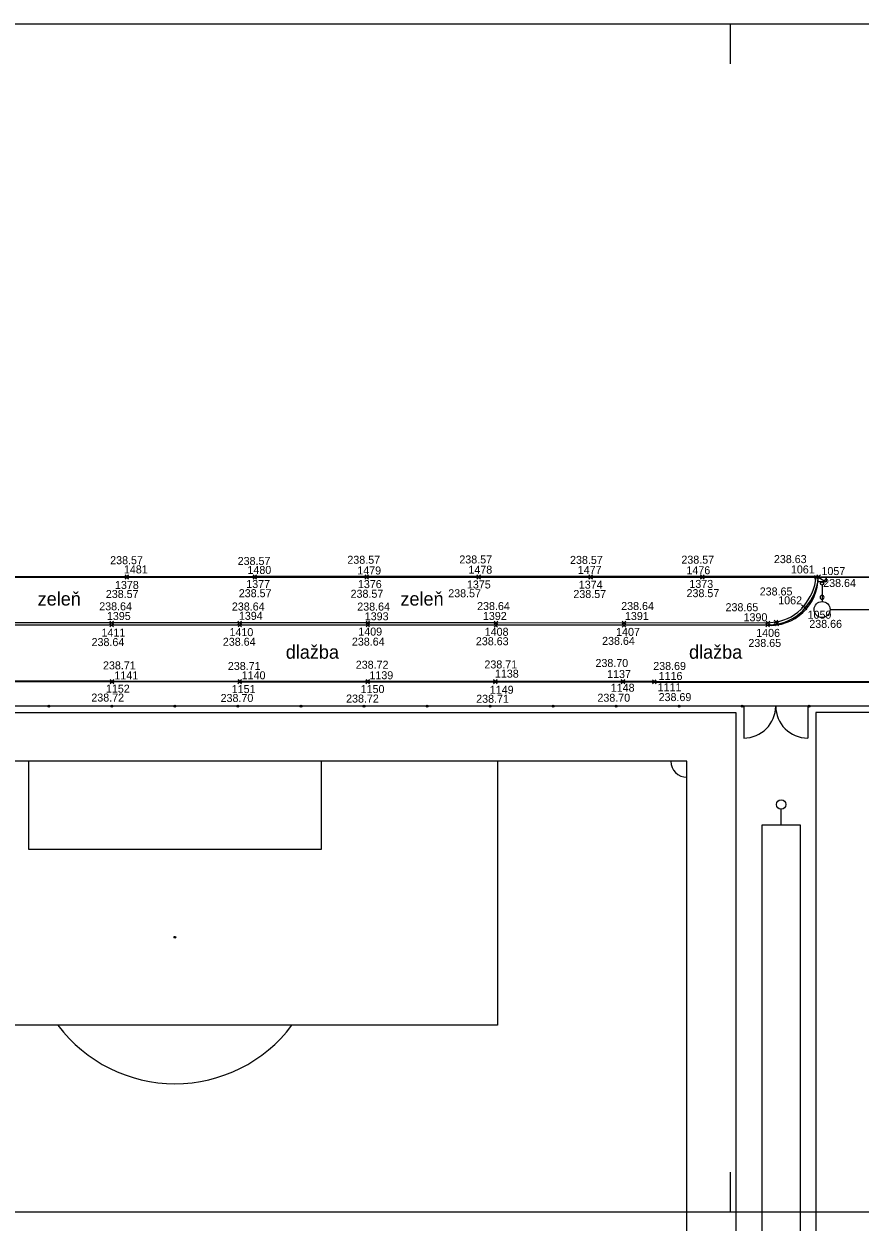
# Model space of a CAD drawing. Extents: x -264205 to -263659, y -1242401 to -1241986.
# Drawn here: x -264092.1 to -264039.8, y -1242219.8 to -1242144.9 of the extents above; entities that cross this region are included whole.
import ezdxf

# ---------------------------------------------------------------- set-up
doc = ezdxf.new("R2010")
doc.units = 0
for name, color, linetype in [('BOD_CISLO_2-1', 7, 'Continuous'), ('BOD_SYMBOL_2-1', 7, 'Continuous'), ('BOD_VYSKA_2-1', 7, 'Continuous'), ('POPIS_2-1', 7, 'Continuous'), ('PROJEKT_OBRUBNIKY_KOMUNIKACIE', 7, 'Continuous'), ('RAM_NA_TLAC_2-1_1-250', 7, 'Continuous'), ('SITUACIA_DSP_2D', 7, 'Continuous'), ('SO_20-4_OBRUBNIKY_HORNA_HRANA', 7, 'Continuous')]:
    doc.layers.add(name, color=color, linetype=linetype)

msp = doc.modelspace()

# ---------------------------------------------------------------- linework, layer by layer
at = {"layer": 'BOD_SYMBOL_2-1'}
for p, q in [((-264085.736, -1242179.559), (-264085.515, -1242179.339)), ((-264085.515, -1242179.559), (-264085.736, -1242179.339)), ((-264085.735, -1242179.603), (-264085.514, -1242179.383)), ((-264085.514, -1242179.603), (-264085.735, -1242179.383)), ((-264077.736, -1242179.556), (-264077.515, -1242179.335)), ((-264077.515, -1242179.556), (-264077.736, -1242179.335)), ((-264077.736, -1242179.6), (-264077.515, -1242179.38)), ((-264077.515, -1242179.6), (-264077.736, -1242179.38)), ((-264070.742, -1242179.596), (-264070.521, -1242179.374)), ((-264070.521, -1242179.596), (-264070.742, -1242179.374)), ((-264070.736, -1242179.549), (-264070.515, -1242179.328)), ((-264070.515, -1242179.549), (-264070.736, -1242179.328)), ((-264063.742, -1242179.548), (-264063.521, -1242179.326)), ((-264063.521, -1242179.548), (-264063.742, -1242179.326)), ((-264063.741, -1242179.596), (-264063.519, -1242179.376)), ((-264063.519, -1242179.596), (-264063.741, -1242179.376)), ((-264056.748, -1242179.552), (-264056.527, -1242179.33)), ((-264056.527, -1242179.552), (-264056.748, -1242179.33)), ((-264056.746, -1242179.597), (-264056.524, -1242179.377)), ((-264056.524, -1242179.597), (-264056.746, -1242179.377)), ((-264049.763, -1242179.556), (-264049.541, -1242179.335)), ((-264049.541, -1242179.556), (-264049.763, -1242179.335)), ((-264049.761, -1242179.6), (-264049.54, -1242179.38)), ((-264049.54, -1242179.6), (-264049.761, -1242179.38)), ((-264042.644, -1242179.597), (-264042.422, -1242179.377)), ((-264042.422, -1242179.597), (-264042.644, -1242179.377)), ((-264042.493, -1242179.552), (-264042.272, -1242179.332)), ((-264042.272, -1242179.552), (-264042.493, -1242179.332)), ((-264043.447, -1242181.421), (-264043.226, -1242181.2)), ((-264043.226, -1242181.421), (-264043.447, -1242181.2)), ((-264043.447, -1242181.421), (-264043.226, -1242181.2)), ((-264043.226, -1242181.421), (-264043.447, -1242181.2)), ((-264043.334, -1242181.511), (-264043.112, -1242181.289)), ((-264043.112, -1242181.511), (-264043.334, -1242181.289)), ((-264043.334, -1242181.511), (-264043.112, -1242181.289)), ((-264043.112, -1242181.511), (-264043.334, -1242181.289)), ((-264086.683, -1242182.59), (-264086.462, -1242182.369)), ((-264086.462, -1242182.59), (-264086.683, -1242182.369)), ((-264086.682, -1242182.441), (-264086.462, -1242182.221)), ((-264086.462, -1242182.441), (-264086.682, -1242182.221)), ((-264078.685, -1242182.441), (-264078.464, -1242182.221)), ((-264078.464, -1242182.441), (-264078.685, -1242182.221)), ((-264078.677, -1242182.585), (-264078.456, -1242182.363)), ((-264078.456, -1242182.585), (-264078.677, -1242182.363)), ((-264070.675, -1242182.59), (-264070.454, -1242182.37)), ((-264070.454, -1242182.59), (-264070.675, -1242182.37)), ((-264070.671, -1242182.447), (-264070.45, -1242182.225)), ((-264070.45, -1242182.447), (-264070.671, -1242182.225)), ((-264062.67, -1242182.593), (-264062.448, -1242182.373)), ((-264062.448, -1242182.593), (-264062.67, -1242182.373)), ((-264062.666, -1242182.451), (-264062.445, -1242182.23)), ((-264062.445, -1242182.451), (-264062.666, -1242182.23)), ((-264054.66, -1242182.6), (-264054.439, -1242182.379)), ((-264054.439, -1242182.6), (-264054.66, -1242182.379)), ((-264054.655, -1242182.454), (-264054.433, -1242182.232)), ((-264054.433, -1242182.454), (-264054.655, -1242182.232)), ((-264045.679, -1242182.588), (-264045.458, -1242182.367)), ((-264045.458, -1242182.588), (-264045.679, -1242182.367)), ((-264045.663, -1242182.445), (-264045.442, -1242182.225)), ((-264045.442, -1242182.445), (-264045.663, -1242182.225)), ((-264045.16, -1242182.377), (-264044.938, -1242182.157)), ((-264044.938, -1242182.377), (-264045.16, -1242182.157)), ((-264045.122, -1242182.516), (-264044.901, -1242182.296)), ((-264044.901, -1242182.516), (-264045.122, -1242182.296)), ((-264086.66, -1242186.09), (-264086.439, -1242185.869)), ((-264086.439, -1242186.09), (-264086.66, -1242185.869)), ((-264086.659, -1242186.136), (-264086.438, -1242185.914)), ((-264086.438, -1242186.136), (-264086.659, -1242185.914)), ((-264078.679, -1242186.144), (-264078.458, -1242185.924)), ((-264078.458, -1242186.144), (-264078.679, -1242185.924)), ((-264078.674, -1242186.1), (-264078.453, -1242185.879)), ((-264078.453, -1242186.1), (-264078.674, -1242185.879)), ((-264070.677, -1242186.144), (-264070.456, -1242185.923)), ((-264070.456, -1242186.144), (-264070.677, -1242185.923)), ((-264070.674, -1242186.096), (-264070.453, -1242185.876)), ((-264070.453, -1242186.096), (-264070.674, -1242185.876)), ((-264062.707, -1242186.099), (-264062.486, -1242185.877)), ((-264062.486, -1242186.099), (-264062.707, -1242185.877)), ((-264062.707, -1242186.141), (-264062.486, -1242185.921)), ((-264062.486, -1242186.141), (-264062.707, -1242185.921)), ((-264054.72, -1242186.096), (-264054.498, -1242185.874)), ((-264054.498, -1242186.096), (-264054.72, -1242185.874)), ((-264054.718, -1242186.14), (-264054.497, -1242185.92)), ((-264054.497, -1242186.14), (-264054.718, -1242185.92)), ((-264052.773, -1242186.103), (-264052.552, -1242185.882)), ((-264052.552, -1242186.103), (-264052.773, -1242185.882)), ((-264052.767, -1242186.149), (-264052.546, -1242185.927)), ((-264052.546, -1242186.149), (-264052.767, -1242185.927))]:
    msp.add_line(p, q, dxfattribs=at)
at = {"layer": 'PROJEKT_OBRUBNIKY_KOMUNIKACIE'}
for p, q in [((-263959.468, -1242179.482), (-264131.568, -1242179.482)), ((-264077.23, -1242179.482), (-264131.568, -1242179.482)), ((-264131.568, -1242179.482), (-263959.468, -1242179.482)), ((-263959.468, -1242179.482), (-264077.23, -1242179.482)), ((-264045.204, -1242182.482), (-264131.568, -1242182.482))]:
    msp.add_line(p, q, dxfattribs=at)
for points in [[(-264117.668, -1242187.932), (-264047.568, -1242187.932), (-264047.568, -1242294.032), (-264117.668, -1242294.032), (-264117.668, -1242187.932)], [(-264042.568, -1242294.032), (-263972.468, -1242294.032), (-263972.468, -1242187.932), (-264042.568, -1242187.932), (-264042.568, -1242294.032)]]:
    msp.add_lwpolyline(points, dxfattribs=at)
msp.add_arc((-264045.411, -1242179.495), 2.994, 266.03136, 0.25001, dxfattribs=at)
at = {"layer": 'RAM_NA_TLAC_2-1_1-250'}
for p, q in [((-264047.913, -1242144.907), (-264047.913, -1242147.407)), ((-264047.913, -1242216.657), (-264047.913, -1242219.157))]:
    msp.add_line(p, q, dxfattribs=at)
msp.add_lwpolyline([(-264147.913, -1242144.907), (-263857.913, -1242144.907), (-263857.913, -1242219.157), (-264147.913, -1242219.157)], close=True, dxfattribs=at)
at = {"layer": 'SITUACIA_DSP_2D'}
for p, q in [((-264077.23, -1242179.482), (-264131.568, -1242179.482)), ((-264131.568, -1242179.482), (-263959.468, -1242179.482)), ((-263959.468, -1242179.482), (-264131.568, -1242179.482)), ((-263959.468, -1242179.482), (-264077.23, -1242179.482)), ((-264042.417, -1242179.482), (-264041.917, -1242179.482)), ((-264042.417, -1242179.772), (-264042.417, -1242179.482)), ((-264042.417, -1242179.482), (-264041.917, -1242179.772)), ((-264042.417, -1242179.482), (-264041.917, -1242179.772)), ((-264041.917, -1242179.482), (-264042.417, -1242179.482)), ((-264041.917, -1242179.482), (-264041.917, -1242179.772)), ((-264041.917, -1242179.772), (-264041.917, -1242179.482)), ((-264041.917, -1242179.772), (-264042.417, -1242179.772)), ((-264042.167, -1242179.972), (-264042.167, -1242181)), ((-264041.667, -1242181.5), (-264014.161, -1242181.5)), ((-264045.204, -1242182.482), (-264131.568, -1242182.482)), ((-263972.068, -1242187.532), (-264118.068, -1242187.532)), ((-264090.436, -1242187.532), (-264090.556, -1242187.532)), ((-264090.496, -1242187.592), (-264090.496, -1242187.472)), ((-264086.497, -1242187.532), (-264086.617, -1242187.532)), ((-264086.557, -1242187.592), (-264086.557, -1242187.472)), ((-264082.558, -1242187.532), (-264082.678, -1242187.532)), ((-264082.618, -1242187.592), (-264082.618, -1242187.472)), ((-264078.619, -1242187.532), (-264078.739, -1242187.532)), ((-264078.679, -1242187.592), (-264078.679, -1242187.472)), ((-264074.68, -1242187.532), (-264074.8, -1242187.532)), ((-264074.74, -1242187.592), (-264074.74, -1242187.472)), ((-264070.741, -1242187.532), (-264070.861, -1242187.532)), ((-264070.801, -1242187.592), (-264070.801, -1242187.472)), ((-264066.802, -1242187.532), (-264066.922, -1242187.532)), ((-264066.862, -1242187.592), (-264066.862, -1242187.472)), ((-264062.863, -1242187.532), (-264062.983, -1242187.532)), ((-264062.923, -1242187.592), (-264062.923, -1242187.472)), ((-264058.924, -1242187.532), (-264059.044, -1242187.532)), ((-264058.984, -1242187.592), (-264058.984, -1242187.472)), ((-264054.986, -1242187.532), (-264055.106, -1242187.532)), ((-264055.046, -1242187.592), (-264055.046, -1242187.472)), ((-264051.047, -1242187.532), (-264051.167, -1242187.532)), ((-264051.107, -1242187.592), (-264051.107, -1242187.472)), ((-264047.108, -1242187.532), (-264047.228, -1242187.532)), ((-264047.168, -1242187.592), (-264047.168, -1242187.472)), ((-264047.068, -1242187.532), (-264047.068, -1242189.532)), ((-264044.568, -1242187.532), (-264045.568, -1242187.532)), ((-264043.068, -1242187.532), (-264043.068, -1242189.532)), ((-264042.908, -1242187.532), (-264043.028, -1242187.532)), ((-264042.968, -1242187.592), (-264042.968, -1242187.472)), ((-264117.668, -1242187.932), (-264047.568, -1242187.932)), ((-264047.568, -1242187.932), (-264047.568, -1242294.032)), ((-263972.468, -1242187.932), (-264042.568, -1242187.932)), ((-264042.568, -1242187.932), (-264042.568, -1242294.032)), ((-264050.618, -1242190.982), (-264114.618, -1242190.982)), ((-264091.778, -1242190.982), (-264091.778, -1242196.482)), ((-264073.458, -1242196.482), (-264073.458, -1242190.982)), ((-264062.458, -1242190.982), (-264062.458, -1242207.482)), ((-264050.618, -1242290.982), (-264050.618, -1242190.982)), ((-264044.727, -1242194.982), (-264044.727, -1242193.982)), ((-264043.527, -1242194.982), (-264045.927, -1242194.982)), ((-264045.927, -1242194.982), (-264045.927, -1242293.982)), ((-264043.527, -1242293.982), (-264043.527, -1242194.982)), ((-264091.778, -1242196.482), (-264073.458, -1242196.482)), ((-264062.458, -1242207.482), (-264102.778, -1242207.482))]:
    msp.add_line(p, q, dxfattribs=at)
for centre, radius in [((-264042.167, -1242179.872), 0.1), ((-264042.167, -1242181.5), 0.5), ((-264090.496, -1242187.532), 0.06), ((-264086.557, -1242187.532), 0.06), ((-264082.618, -1242187.532), 0.06), ((-264078.679, -1242187.532), 0.06), ((-264074.74, -1242187.532), 0.06), ((-264070.801, -1242187.532), 0.06), ((-264066.862, -1242187.532), 0.06), ((-264062.923, -1242187.532), 0.06), ((-264058.984, -1242187.532), 0.06), ((-264055.046, -1242187.532), 0.06), ((-264051.107, -1242187.532), 0.06), ((-264047.168, -1242187.532), 0.06), ((-264042.968, -1242187.532), 0.06), ((-264044.727, -1242193.682), 0.3), ((-264082.618, -1242201.982), 0.06)]:
    msp.add_circle(centre, radius, dxfattribs=at)
for centre, radius, start, end in [((-264045.412, -1242179.495), 2.994, 266.03136, 0.25001), ((-264042.167, -1242180.736), 0.125, 0, 180), ((-264042.167, -1242180.736), 0.125, 180, 0), ((-264047.068, -1242187.532), 2, 270, 360), ((-264043.068, -1242187.532), 2, 180, 270), ((-264050.618, -1242190.982), 1, 180, 270), ((-264082.618, -1242201.982), 0.0303, 90, 270), ((-264082.618, -1242201.982), 0.0303, 270, 90), ((-264082.618, -1242201.982), 9.15, 216.94821, 323.05179)]:
    msp.add_arc(centre, radius, start, end, dxfattribs=at)
at = {"layer": 'SO_20-4_OBRUBNIKY_HORNA_HRANA'}
for p, q in [((-264045.568, -1242182.477), (-264045.012, -1242182.406)), ((-264045.552, -1242182.335), (-264045.049, -1242182.267))]:
    msp.add_line(p, q, dxfattribs=at)
for points in [[(-264042.383, -1242179.442), (-264049.652, -1242179.445), (-264056.638, -1242179.441), (-264063.632, -1242179.437), (-264070.626, -1242179.438), (-264077.626, -1242179.445), (-264085.626, -1242179.449), (-264093.626, -1242179.439), (-264101.625, -1242179.445), (-264109.615, -1242179.435), (-264117.612, -1242179.431), (-264120.602, -1242179.426), (-264126.121, -1242179.433), (-264131.733, -1242179.426)], [(-264045.552, -1242182.335), (-264054.544, -1242182.343), (-264062.556, -1242182.34), (-264070.561, -1242182.336), (-264078.574, -1242182.331), (-264086.572, -1242182.331), (-264094.586, -1242182.329), (-264102.573, -1242182.329), (-264108.577, -1242182.332), (-264114.576, -1242182.338), (-264117.588, -1242182.342), (-264119.607, -1242182.346), (-264120.588, -1242182.345), (-264122.586, -1242182.345), (-264127.589, -1242182.338), (-264131.6, -1242182.327), (-264131.589, -1242179.471)], [(-264042.533, -1242179.487), (-264049.65, -1242179.49), (-264056.635, -1242179.487), (-264063.63, -1242179.486), (-264070.632, -1242179.485), (-264077.626, -1242179.49), (-264085.624, -1242179.493), (-264093.625, -1242179.486), (-264101.626, -1242179.485), (-264109.614, -1242179.478), (-264117.62, -1242179.479), (-264120.6, -1242179.475), (-264126.132, -1242179.477), (-264131.589, -1242179.471)], [(-264045.568, -1242182.477), (-264054.55, -1242182.489), (-264062.559, -1242182.483), (-264070.564, -1242182.48), (-264078.567, -1242182.474), (-264086.573, -1242182.479), (-264094.593, -1242182.473), (-264102.574, -1242182.476), (-264108.578, -1242182.479), (-264114.569, -1242182.481), (-264117.587, -1242182.486), (-264119.603, -1242182.49), (-264120.584, -1242182.487), (-264122.587, -1242182.488), (-264127.582, -1242182.481), (-264131.601, -1242182.479), (-264131.604, -1242183.314), (-264131.618, -1242187.312), (-264131.63, -1242191.337)], [(-264052.662, -1242185.992), (-264054.609, -1242185.985), (-264062.596, -1242185.988), (-264070.563, -1242185.986), (-264078.563, -1242185.989), (-264086.55, -1242185.979), (-264094.528, -1242185.977), (-264102.531, -1242185.982), (-264108.517, -1242185.984), (-264114.496, -1242185.984), (-264120.541, -1242185.983), (-264120.522, -1242190.785)], [(-264052.656, -1242186.038), (-264054.607, -1242186.03), (-264062.596, -1242186.031), (-264070.567, -1242186.033), (-264078.568, -1242186.034), (-264086.548, -1242186.025), (-264094.528, -1242186.023), (-264102.527, -1242186.027), (-264108.524, -1242186.03), (-264114.499, -1242186.031), (-264120.495, -1242186.026), (-264120.474, -1242190.807)], [(-264052.662, -1242185.992), (-264034.314, -1242185.992), (-264016.879, -1242186.004), (-263991.714, -1242185.977), (-263970.772, -1242185.99)], [(-264052.656, -1242186.038), (-264034.308, -1242186.038), (-264016.873, -1242186.05), (-263991.708, -1242186.023), (-263970.772, -1242186.036)]]:
    msp.add_lwpolyline(points, dxfattribs=at)
for centre, major_axis, ratio, start_param, end_param in [((-264045.907, -1242179.088), (-0.355, 3.38), 0.999875, 3.895107, 4.490115), ((-264045.895, -1242179.095), (3.252, 1.371), 0.999954, 5.172465, 5.785827), ((-264045.441, -1242179.553), (1.199, -2.466), 0.999992, 5.974171, 6.705992), ((-264045.448, -1242179.537), (2.831, -0.636), 0.999973, 5.084093, 5.807053)]:
    msp.add_ellipse(centre, major_axis=major_axis, ratio=ratio, start_param=start_param, end_param=end_param, dxfattribs=at)

# ---------------------------------------------------------------- texts
at = {"layer": 'BOD_CISLO_2-1'}
for s, p in [('1481', (-264085.809, -1242179.243)), ('1480', (-264078.086, -1242179.276)), ('1479', (-264071.22, -1242179.308)), ('1478', (-264064.274, -1242179.259)), ('1477', (-264057.439, -1242179.275)), ('1476', (-264050.646, -1242179.294)), ('1061', (-264044.117, -1242179.244)), ('1057', (-264042.206, -1242179.346)), ('1378', (-264086.367, -1242180.213)), ('1377', (-264078.161, -1242180.153)), ('1376', (-264071.182, -1242180.16)), ('1375', (-264064.368, -1242180.183)), ('1374', (-264057.375, -1242180.195)), ('1373', (-264050.463, -1242180.149)), ('1062', (-264044.909, -1242181.175)), ('1395', (-264086.872, -1242182.155)), ('1394', (-264078.622, -1242182.142)), ('1393', (-264070.754, -1242182.171)), ('1392', (-264063.369, -1242182.151)), ('1391', (-264054.49, -1242182.154)), ('1390', (-264047.075, -1242182.231)), ('1059', (-264043.073, -1242182.074)), ('1411', (-264087.209, -1242183.188)), ('1410', (-264079.209, -1242183.162)), ('1409', (-264071.157, -1242183.128)), ('1408', (-264063.255, -1242183.14)), ('1407', (-264055.042, -1242183.144)), ('1406', (-264046.286, -1242183.208)), ('1141', (-264086.405, -1242185.865)), ('1140', (-264078.445, -1242185.858)), ('1139', (-264070.462, -1242185.856)), ('1138', (-264062.617, -1242185.756)), ('1137', (-264055.604, -1242185.779)), ('1116', (-264052.384, -1242185.901)), ('1152', (-264086.933, -1242186.695)), ('1151', (-264079.071, -1242186.72)), ('1150', (-264071.011, -1242186.719)), ('1149', (-264062.938, -1242186.761)), ('1148', (-264055.377, -1242186.635)), ('1111', (-264052.447, -1242186.602))]:
    msp.add_text(s, height=0.5, dxfattribs=at).set_placement(p)
at = {"layer": 'BOD_VYSKA_2-1'}
for s, p in [('238.57', (-264086.667, -1242178.666)), ('238.57', (-264078.698, -1242178.714)), ('238.57', (-264071.841, -1242178.64)), ('238.57', (-264064.842, -1242178.62)), ('238.57', (-264057.922, -1242178.649)), ('238.57', (-264050.963, -1242178.634)), ('238.63', (-264045.179, -1242178.598)), ('238.57', (-264086.938, -1242180.778)), ('238.57', (-264078.628, -1242180.729)), ('238.57', (-264071.64, -1242180.764)), ('238.57', (-264065.535, -1242180.733)), ('238.57', (-264057.713, -1242180.781)), ('238.57', (-264050.64, -1242180.726)), ('238.65', (-264046.067, -1242180.62)), ('238.64', (-264042.098, -1242180.09)), ('238.64', (-264087.352, -1242181.548)), ('238.64', (-264079.059, -1242181.56)), ('238.64', (-264071.223, -1242181.565)), ('238.64', (-264063.732, -1242181.532)), ('238.64', (-264054.724, -1242181.529)), ('238.65', (-264048.202, -1242181.605)), ('238.66', (-264042.967, -1242182.645)), ('238.64', (-264087.83, -1242183.782)), ('238.64', (-264079.625, -1242183.764)), ('238.64', (-264071.558, -1242183.754)), ('238.63', (-264063.808, -1242183.73)), ('238.64', (-264055.918, -1242183.709)), ('238.65', (-264046.774, -1242183.837)), ('238.71', (-264087.116, -1242185.24)), ('238.71', (-264079.311, -1242185.277)), ('238.72', (-264071.316, -1242185.199)), ('238.71', (-264063.275, -1242185.18)), ('238.70', (-264056.333, -1242185.091)), ('238.69', (-264052.722, -1242185.275)), ('238.72', (-264087.845, -1242187.251)), ('238.70', (-264079.765, -1242187.276)), ('238.72', (-264071.92, -1242187.312)), ('238.71', (-264063.789, -1242187.326)), ('238.70', (-264056.211, -1242187.261)), ('238.69', (-264052.385, -1242187.221))]:
    msp.add_text(s, height=0.5, dxfattribs=at).set_placement(p)
at = {"layer": 'POPIS_2-1'}
for s, p in [('zeleň', (-264091.2, -1242181.251)), ('zeleň', (-264068.524, -1242181.251)), ('dlažba', (-264075.69, -1242184.573)), ('dlažba', (-264050.485, -1242184.573))]:
    msp.add_text(s, height=0.8438, dxfattribs=at).set_placement(p)

doc.saveas('drawing.dxf')
